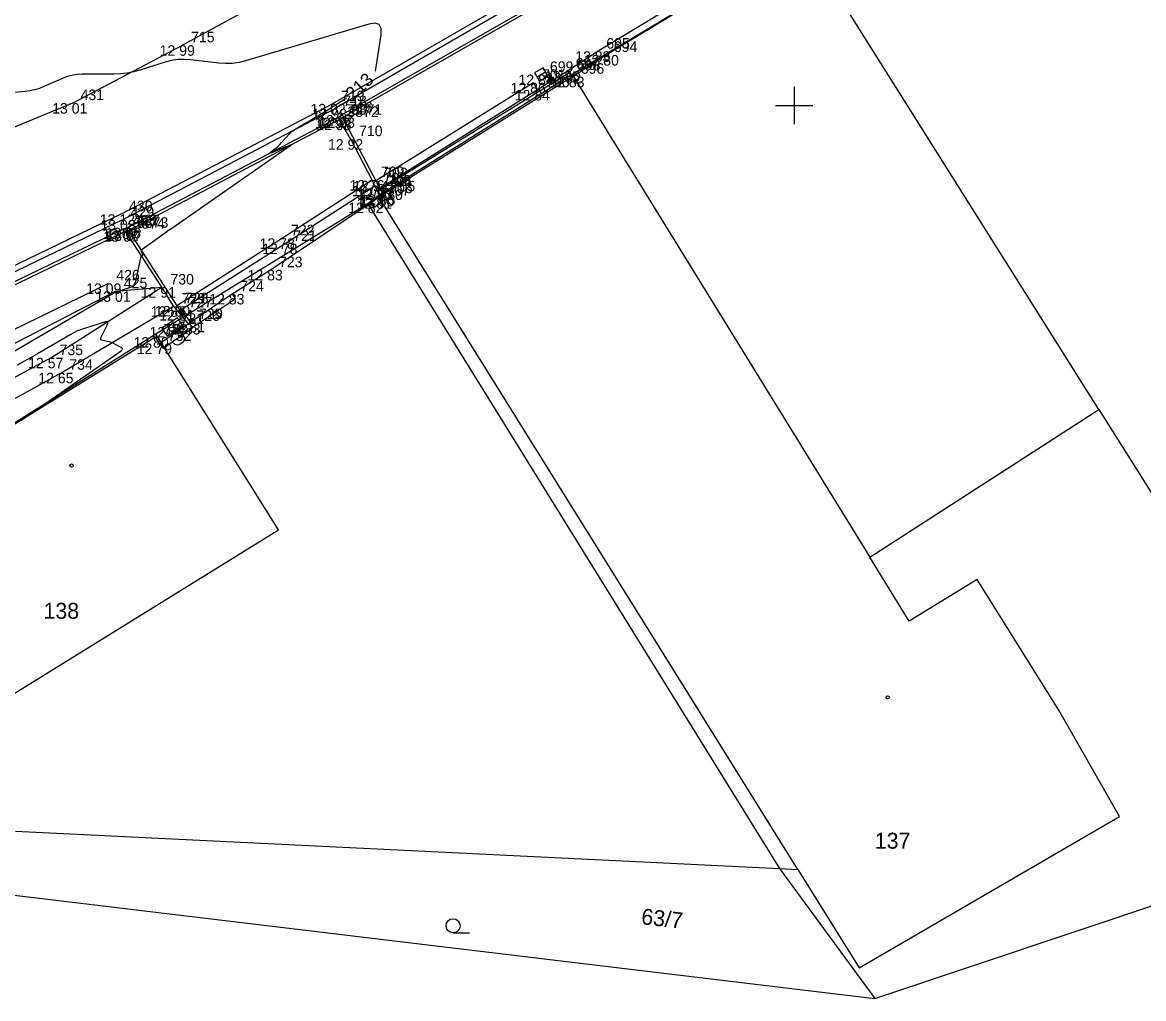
# Model space of a CAD drawing. Extents: x -703403 to -701924, y -1022520 to -1021856.
# Drawn here: x -703295.54 to -703265.7, y -1022198.78 to -1022172.79 of the extents above; entities that cross this region are included whole.
import ezdxf

# ---------------------------------------------------------------- set-up
doc = ezdxf.new("R2010")
doc.units = 0
for name, color, linetype in [('Ex_Contour Labels', 7, 'Continuous'), ('Ex_Major Contours', 7, 'Continuous'), ('Ex_Minor Contours', 7, 'Continuous'), ('Z_body', 7, 'Continuous'), ('Z_body_cisla', 7, 'Continuous'), ('Z_body_vysky_redukovane', 7, 'Continuous'), ('Z_budova', 7, 'Continuous'), ('Z_chodnik', 7, 'Continuous'), ('Z_hektometricka_sit', 7, 'Continuous'), ('Z_hrany_paty', 7, 'Continuous'), ('Z_katastr_cisla_pozemkova', 7, 'Continuous'), ('Z_katastr_cisla_stavebni', 7, 'Continuous'), ('Z_katastr_hranice', 7, 'Continuous'), ('Z_katastr_vnitrni_kresba', 7, 'Continuous'), ('Z_katastr_znacky_budov', 7, 'Continuous'), ('Z_katastr_znacky_kultur', 7, 'Continuous'), ('Z_komunikace', 7, 'Continuous'), ('Z_komunikace_osa', 7, 'Continuous'), ('Z_obruba', 7, 'Continuous'), ('Z_pilire', 7, 'Continuous'), ('Z_ploty', 7, 'Continuous'), ('Z_ploty_znacky', 7, 'Continuous'), ('Z_rozhranni', 7, 'Continuous'), ('Z_site_kanalizace_znaky', 7, 'Continuous'), ('Z_svodidla', 7, 'Continuous'), ('Z_vstupy', 7, 'Continuous'), ('Z_zlabek', 7, 'Continuous')]:
    doc.layers.add(name, color=color, linetype=linetype)

# ---------------------------------------------------------------- blocks, each defined once
blk = doc.blocks.new('POINT_DISPLAY')
blk.add_line((0, 0), (0, 0))
blk = doc.blocks.new('Z666')
for p, q in [((-0.25, 0.13), (-0.25, -0.13)), ((0.25, 0.13), (-0.25, 0.13)), ((0.25, -0.13), (0.25, 0.13)), ((-0.25, -0.13), (0.25, -0.13))]:
    blk.add_line(p, q)
blk = doc.blocks.new('Z46260')
for p, q in [((0.13, 0.13), (-0.13, 0.13)), ((-0.13, 0.13), (-0.13, -0.13)), ((0.13, 0), (-0.13, 0)), ((0.13, -0.13), (0.13, 0.13)), ((-0.13, -0.13), (0.13, -0.13))]:
    blk.add_line(p, q)
blk = doc.blocks.new('Z216')
for p, q in [((-0.17, 0), (-0.15, 0.1)), ((-0.15, 0.1), (-0.1, 0.15)), ((-0.1, 0.15), (-0.03, 0.17)), ((-0.03, 0.17), (0.03, 0.17)), ((0.03, 0.17), (0.1, 0.15)), ((0.1, 0.15), (0.15, 0.1)), ((0.15, 0.1), (0.17, 0))]:
    blk.add_line(p, q)

msp = doc.modelspace()

# ---------------------------------------------------------------- linework, layer by layer
at = {"layer": 'Ex_Major Contours'}
for points in [[(-703286.143, -1022174.09), (-703285.992, -1022173.119), (-703285.989, -1022172.952), (-703286.042, -1022172.849), (-703286.152, -1022172.81), (-703286.317, -1022172.836), (-703289.599, -1022173.815), (-703289.775, -1022173.858), (-703289.953, -1022173.883), (-703290.133, -1022173.889), (-703290.314, -1022173.877), (-703291.058, -1022173.788), (-703291.231, -1022173.776), (-703291.403, -1022173.783), (-703291.573, -1022173.808), (-703291.741, -1022173.852), (-703292.41, -1022174.064), (-703292.579, -1022174.11), (-703292.749, -1022174.144), (-703292.922, -1022174.164), (-703293.096, -1022174.171), (-703293.96, -1022174.173), (-703294.092, -1022174.18), (-703294.222, -1022174.201), (-703294.349, -1022174.235), (-703294.474, -1022174.282), (-703294.965, -1022174.498), (-703295.089, -1022174.547), (-703295.215, -1022174.585), (-703295.345, -1022174.614), (-703295.477, -1022174.631), (-703298.928, -1022174.96)], [(-703296.239, -1022181.823), (-703293.136, -1022180.012), (-703293.117, -1022180.001), (-703293.098, -1022179.992), (-703293.079, -1022179.984), (-703293.059, -1022179.977), (-703292.978, -1022179.952), (-703292.957, -1022179.945), (-703292.937, -1022179.938), (-703292.917, -1022179.931), (-703292.897, -1022179.924), (-703292.643, -1022179.827), (-703292.599, -1022179.805), (-703292.564, -1022179.774), (-703292.539, -1022179.735), (-703292.523, -1022179.687), (-703292.378, -1022179.013), (-703292.376, -1022179.008), (-703292.373, -1022179.004), (-703292.369, -1022179.001), (-703292.364, -1022178.999), (-703292.342, -1022178.993), (-703292.337, -1022178.992), (-703292.334, -1022178.989), (-703292.334, -1022178.985), (-703292.335, -1022178.98), (-703292.372, -1022178.886), (-703292.376, -1022178.869), (-703292.375, -1022178.854), (-703292.368, -1022178.841), (-703292.355, -1022178.829), (-703291.894, -1022178.498), (-703291.812, -1022178.44), (-703291.73, -1022178.381), (-703291.647, -1022178.323), (-703291.565, -1022178.266), (-703288.392, -1022176.06), (-703288.379, -1022176.05), (-703288.376, -1022176.046), (-703288.382, -1022176.046), (-703288.397, -1022176.052), (-703288.477, -1022176.084), (-703288.497, -1022176.092), (-703288.517, -1022176.1), (-703288.537, -1022176.108), (-703288.557, -1022176.117), (-703288.925, -1022176.27), (-703288.959, -1022176.282), (-703288.973, -1022176.283), (-703288.966, -1022176.271), (-703288.938, -1022176.248), (-703288.788, -1022176.131), (-703288.751, -1022176.1), (-703288.716, -1022176.069), (-703288.681, -1022176.036), (-703288.649, -1022176.001), (-703288.422, -1022175.751), (-703288.39, -1022175.718), (-703288.356, -1022175.687), (-703288.319, -1022175.659), (-703288.281, -1022175.634), (-703288.122, -1022175.539), (-703288.082, -1022175.515), (-703288.043, -1022175.492), (-703288.003, -1022175.468), (-703287.963, -1022175.444), (-703287.456, -1022175.142), (-703287.358, -1022175.083), (-703287.261, -1022175.023), (-703287.165, -1022174.963), (-703287.069, -1022174.901), (-703286.915, -1022174.802)]]:
    msp.add_lwpolyline(points, dxfattribs=at)
at = {"layer": 'Ex_Minor Contours'}
msp.add_lwpolyline([(-703295.579, -1022183.387), (-703292.91, -1022181.538), (-703292.883, -1022181.513), (-703292.875, -1022181.489), (-703292.885, -1022181.466), (-703292.915, -1022181.444), (-703293.077, -1022181.356), (-703293.115, -1022181.337), (-703293.153, -1022181.321), (-703293.192, -1022181.308), (-703293.233, -1022181.297), (-703293.397, -1022181.261), (-703293.431, -1022181.249), (-703293.449, -1022181.229), (-703293.453, -1022181.202), (-703293.441, -1022181.168), (-703293.283, -1022180.854), (-703293.264, -1022180.8), (-703293.269, -1022180.768), (-703293.3, -1022180.757), (-703293.357, -1022180.768), (-703293.862, -1022180.928), (-703293.968, -1022180.965), (-703294.071, -1022181.007), (-703294.172, -1022181.055), (-703294.271, -1022181.109), (-703295.142, -1022181.618), (-703295.32, -1022181.72), (-703295.499, -1022181.821), (-703295.679, -1022181.92)], dxfattribs=at)
at = {"layer": 'Z_budova'}
for p, q in [((-703280.91, -1022174.24), (-703285.94, -1022177.37)), ((-703286, -1022177.41), (-703286.08, -1022177.47)), ((-703285.94, -1022177.37), (-703286, -1022177.41)), ((-703286.08, -1022177.47), (-703285.99, -1022177.59)), ((-703292, -1022181.17), (-703300.59, -1022186.49)), ((-703291.89, -1022181.34), (-703292, -1022181.17)), ((-703291.89, -1022181.34), (-703291.8, -1022181.46))]:
    msp.add_line(p, q, dxfattribs=at)
at = {"layer": 'Z_chodnik'}
for p, q in [((-703281.03, -1022174.09), (-703281.83, -1022174.59)), ((-703281.83, -1022174.59), (-703286.03, -1022177.21))]:
    msp.add_line(p, q, dxfattribs=at)
at = {"layer": 'Z_hektometricka_sit'}
for p, q in [((-703275, -1022174.5), (-703275, -1022175.5)), ((-703275.5, -1022175), (-703274.5, -1022175))]:
    msp.add_line(p, q, dxfattribs=at)
at = {"layer": 'Z_hrany_paty'}
for p, q in [((-703297.17, -1022182.07), (-703293.06, -1022179.95)), ((-703293.06, -1022179.95), (-703291.83, -1022179.84))]:
    msp.add_line(p, q, dxfattribs=at)
at = {"layer": 'Z_katastr_hranice'}
for p, q in [((-703274.81, -1022170.51), (-703280.91, -1022174.18)), ((-703266.89, -1022183.1), (-703274.81, -1022170.51)), ((-703280.91, -1022174.18), (-703286.07, -1022177.41)), ((-703286.07, -1022177.41), (-703286.35, -1022177.62)), ((-703286.35, -1022177.62), (-703291.99, -1022181.09)), ((-703286.35, -1022177.62), (-703275.39, -1022195.32)), ((-703291.99, -1022181.09), (-703300.54, -1022186.47)), ((-703272.99, -1022187.03), (-703266.89, -1022183.1)), ((-703266.89, -1022183.1), (-703259.79, -1022194.4)), ((-703271.94, -1022188.73), (-703272.99, -1022187.03)), ((-703270.13, -1022187.62), (-703271.94, -1022188.73)), ((-703267.96, -1022191.1), (-703270.13, -1022187.62)), ((-703266.34, -1022193.93), (-703267.96, -1022191.1)), ((-703319.68, -1022193.15), (-703272.85, -1022198.78)), ((-703273.27, -1022197.96), (-703266.34, -1022193.93)), ((-703295.72, -1022194.32), (-703275.39, -1022195.32)), ((-703272.85, -1022198.78), (-703259.79, -1022194.4)), ((-703275.39, -1022195.32), (-703272.85, -1022198.78)), ((-703275.39, -1022195.32), (-703274.9, -1022195.34)), ((-703274.9, -1022195.34), (-703273.27, -1022197.96))]:
    msp.add_line(p, q, dxfattribs=at)
at = {"layer": 'Z_katastr_vnitrni_kresba'}
for p, q in [((-703280.91, -1022174.18), (-703272.99, -1022187.03)), ((-703278.08, -1022190.24), (-703286.07, -1022177.41)), ((-703288.72, -1022186.3), (-703291.99, -1022181.09)), ((-703297.36, -1022191.65), (-703288.72, -1022186.3)), ((-703274.9, -1022195.34), (-703278.08, -1022190.24))]:
    msp.add_line(p, q, dxfattribs=at)
at = {"layer": 'Z_katastr_znacky_budov'}
for centre in [(-703294.232, -1022184.59), (-703272.512, -1022190.76)]:
    msp.add_circle(centre, 0.0437, dxfattribs=at)
at = {"layer": 'Z_katastr_znacky_kultur'}
msp.add_line((-703284.078, -1022197.03), (-703283.641, -1022197.03), dxfattribs=at)
msp.add_circle((-703284.078, -1022196.842), 0.187, dxfattribs=at)
at = {"layer": 'Z_komunikace'}
for p, q in [((-703282.29, -1022172.07), (-703287.29, -1022174.96)), ((-703292.92, -1022177.9), (-703287.29, -1022174.96)), ((-703292.92, -1022177.9), (-703298.28, -1022180.49))]:
    msp.add_line(p, q, dxfattribs=at)
at = {"layer": 'Z_komunikace_osa'}
for p, q in [((-703283.89, -1022169.36), (-703291.28, -1022173.4)), ((-703294.21, -1022174.94), (-703291.28, -1022173.4)), ((-703294.21, -1022174.94), (-703299.59, -1022177.17))]:
    msp.add_line(p, q, dxfattribs=at)
at = {"layer": 'Z_obruba'}
for p, q in [((-703282.25, -1022172.21), (-703287.23, -1022175.09)), ((-703287.02, -1022175.32), (-703282.07, -1022172.49)), ((-703281, -1022174.14), (-703286.01, -1022177.24)), ((-703292.88, -1022178.05), (-703287.23, -1022175.09)), ((-703287.11, -1022175.38), (-703287.02, -1022175.32)), ((-703287.02, -1022175.32), (-703286.13, -1022177.01)), ((-703292.72, -1022178.33), (-703287.11, -1022175.38)), ((-703286.13, -1022177.01), (-703286.03, -1022177.21)), ((-703286.03, -1022177.21), (-703286.01, -1022177.24)), ((-703286.01, -1022177.24), (-703285.94, -1022177.37)), ((-703292.88, -1022178.05), (-703298.2, -1022180.61)), ((-703298.01, -1022180.87), (-703292.8, -1022178.35)), ((-703292.8, -1022178.35), (-703292.72, -1022178.33)), ((-703291.83, -1022179.84), (-703292.8, -1022178.35)), ((-703291.52, -1022180.35), (-703291.83, -1022179.84)), ((-703291.52, -1022180.35), (-703291.13, -1022180.82))]:
    msp.add_line(p, q, dxfattribs=at)
at = {"layer": 'Z_ploty'}
for p, q in [((-703286.08, -1022177.47), (-703286.26, -1022177.59)), ((-703286.17, -1022177.72), (-703286.26, -1022177.59)), ((-703285.99, -1022177.59), (-703286.17, -1022177.72)), ((-703291.06, -1022180.76), (-703289.96, -1022180.02)), ((-703289.96, -1022180.02), (-703289.88, -1022180.15)), ((-703290.97, -1022180.88), (-703289.88, -1022180.15)), ((-703291.89, -1022181.34), (-703291.13, -1022180.82)), ((-703291.8, -1022181.46), (-703291.03, -1022180.94)), ((-703291.13, -1022180.82), (-703291.06, -1022180.76)), ((-703291.03, -1022180.94), (-703290.97, -1022180.88))]:
    msp.add_line(p, q, dxfattribs=at)
at = {"layer": 'Z_rozhranni'}
for p, q in [((-703286.8, -1022175.9), (-703287.11, -1022175.38)), ((-703286.23, -1022176.99), (-703286.8, -1022175.9)), ((-703286.16, -1022177.14), (-703286.23, -1022176.99)), ((-703286, -1022177.41), (-703286.16, -1022177.14)), ((-703292.72, -1022178.33), (-703291.43, -1022180.34)), ((-703291.34, -1022180.45), (-703291.43, -1022180.34)), ((-703291.34, -1022180.45), (-703291.06, -1022180.76))]:
    msp.add_line(p, q, dxfattribs=at)
at = {"layer": 'Z_svodidla'}
msp.add_line((-703297.52, -1022181.82), (-703293.26, -1022179.74), dxfattribs=at)
at = {"layer": 'Z_vstupy'}
for p, q in [((-703280.02, -1022173.66), (-703276.98, -1022171.82)), ((-703280.91, -1022174.24), (-703280.02, -1022173.66)), ((-703288.94, -1022179.38), (-703286.26, -1022177.59)), ((-703289.96, -1022180.02), (-703288.94, -1022179.38))]:
    msp.add_line(p, q, dxfattribs=at)
at = {"layer": 'Z_zlabek'}
for p, q in [((-703276.14, -1022171.09), (-703280.22, -1022173.56)), ((-703287.06, -1022175.26), (-703282.11, -1022172.43)), ((-703280.22, -1022173.56), (-703281.03, -1022174.09)), ((-703281.03, -1022174.09), (-703281, -1022174.14)), ((-703281.94, -1022174.4), (-703286.13, -1022177.01)), ((-703281.94, -1022174.4), (-703281.83, -1022174.59)), ((-703281, -1022174.14), (-703280.91, -1022174.24)), ((-703287.15, -1022175.33), (-703292.74, -1022178.26)), ((-703287.15, -1022175.33), (-703287.06, -1022175.26)), ((-703286.23, -1022176.99), (-703288.62, -1022178.54)), ((-703288.55, -1022178.68), (-703286.16, -1022177.14)), ((-703298.04, -1022180.8), (-703292.83, -1022178.28)), ((-703292.83, -1022178.28), (-703292.74, -1022178.26)), ((-703288.62, -1022178.54), (-703291.43, -1022180.34)), ((-703291.34, -1022180.45), (-703288.55, -1022178.68)), ((-703294.78, -1022181.72), (-703291.83, -1022179.84)), ((-703294.51, -1022182.12), (-703291.52, -1022180.35)), ((-703294.78, -1022181.72), (-703298.53, -1022183.76)), ((-703298.36, -1022184.25), (-703294.51, -1022182.12))]:
    msp.add_line(p, q, dxfattribs=at)

# ---------------------------------------------------------------- block references
at = {"layer": 'Z_body'}
for p in [(-703291.28, -1022173.4), (-703280.22, -1022173.56), (-703280.02, -1022173.66), (-703281.03, -1022174.09), (-703281.94, -1022174.4), (-703281.73, -1022174.18), (-703281, -1022174.14), (-703280.91, -1022174.24), (-703281.83, -1022174.59), (-703294.21, -1022174.94), (-703287.29, -1022174.96), (-703287.23, -1022175.09), (-703287.15, -1022175.33), (-703287.06, -1022175.26), (-703287.02, -1022175.32), (-703287.11, -1022175.38), (-703286.8, -1022175.9), (-703286.23, -1022176.99), (-703286.13, -1022177.01), (-703286.16, -1022177.14), (-703286.03, -1022177.21), (-703286.01, -1022177.24), (-703286, -1022177.41), (-703285.94, -1022177.37), (-703286.26, -1022177.59), (-703286.08, -1022177.47), (-703292.92, -1022177.9), (-703292.88, -1022178.05), (-703292.83, -1022178.28), (-703292.74, -1022178.26), (-703292.8, -1022178.35), (-703292.72, -1022178.33), (-703288.62, -1022178.54), (-703288.55, -1022178.68), (-703288.94, -1022179.38), (-703293.26, -1022179.74), (-703293.06, -1022179.95), (-703291.83, -1022179.84), (-703289.96, -1022180.02), (-703291.52, -1022180.35), (-703291.43, -1022180.34), (-703291.34, -1022180.45), (-703291.55, -1022180.9), (-703291.13, -1022180.82), (-703291.06, -1022180.76), (-703292, -1022181.17), (-703291.89, -1022181.34), (-703294.78, -1022181.72), (-703294.51, -1022182.12)]:
    msp.add_blockref('POINT_DISPLAY', p, dxfattribs=at)
at = {"layer": 'Z_pilire', "rotation": 33.3}
msp.add_blockref('Z666', (-703291.55, -1022180.9), dxfattribs=at)
at = {"layer": 'Z_ploty_znacky'}
for p, rotation in [((-703290.42, -1022180.51), -146.30000000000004), ((-703291.41, -1022181.2), -145.5)]:
    msp.add_blockref('Z216', p, dxfattribs=dict(at, rotation=rotation))
at = {"layer": 'Z_site_kanalizace_znaky', "rotation": 30.599999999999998}
msp.add_blockref('Z46260', (-703281.73, -1022174.18), dxfattribs=at)

# ---------------------------------------------------------------- texts
at = {"layer": 'Ex_Contour Labels'}
msp.add_text('213', height=0.35, rotation=42.197, dxfattribs=at).set_placement((-703286.742, -1022174.885))
at = {"layer": 'Z_body_cisla'}
for s, p in [('715', (-703291.05, -1022173.32)), ('695', (-703280, -1022173.49)), ('694', (-703279.8, -1022173.58)), ('699', (-703281.5, -1022174.11)), ('697', (-703280.81, -1022174.02)), ('698', (-703280.78, -1022174.07)), ('701', (-703281.71, -1022174.32)), ('696', (-703280.68, -1022174.16)), ('700', (-703281.6, -1022174.52)), ('431', (-703293.99, -1022174.86)), ('719', (-703287.06, -1022174.89)), ('718', (-703287, -1022175.02)), ('717', (-703286.92, -1022175.25)), ('3872', (-703286.89, -1022175.31)), ('716', (-703286.84, -1022175.19)), ('3871', (-703286.8, -1022175.25)), ('710', (-703286.58, -1022175.82)), ('709', (-703286, -1022176.91)), ('708', (-703285.93, -1022177.07)), ('702', (-703285.91, -1022176.94)), ('707', (-703285.85, -1022177.4)), ('703', (-703285.81, -1022177.14)), ('704', (-703285.79, -1022177.17)), ('706', (-703285.78, -1022177.34)), ('705', (-703285.71, -1022177.29)), ('720', (-703286.04, -1022177.52)), ('430', (-703292.7, -1022177.82)), ('429', (-703292.66, -1022177.98)), ('428', (-703292.6, -1022178.2)), ('3874', (-703292.58, -1022178.28)), ('427', (-703292.51, -1022178.19)), ('3873', (-703292.49, -1022178.26)), ('722', (-703288.39, -1022178.46)), ('721', (-703288.33, -1022178.61)), ('723', (-703288.71, -1022179.31)), ('426', (-703293.04, -1022179.66)), ('730', (-703291.6, -1022179.77)), ('425', (-703292.84, -1022179.87)), ('724', (-703289.74, -1022179.95)), ('729', (-703291.3, -1022180.28)), ('728', (-703291.21, -1022180.27)), ('727', (-703291.11, -1022180.38)), ('731', (-703291.33, -1022180.82)), ('726', (-703290.91, -1022180.74)), ('725', (-703290.84, -1022180.69)), ('733', (-703291.78, -1022181.1)), ('732', (-703291.67, -1022181.27)), ('735', (-703294.55, -1022181.65)), ('734', (-703294.29, -1022182.04))]:
    msp.add_text(s, height=0.28, dxfattribs=at).set_placement(p)
at = {"layer": 'Z_body_vysky_redukovane'}
for s, p in [('12 99', (-703291.887, -1022173.68)), ('12 83', (-703280.827, -1022173.84)), ('12 80', (-703280.603, -1022173.94)), ('12 85', (-703281.637, -1022174.37)), ('12 92', (-703281.607, -1022174.42)), ('12 86', (-703282.547, -1022174.68)), ('12 84', (-703282.337, -1022174.46)), ('12 83', (-703281.517, -1022174.52)), ('12 84', (-703282.437, -1022174.87)), ('13 01', (-703294.747, -1022175.22)), ('13 02', (-703287.873, -1022175.24)), ('12 98', (-703287.837, -1022175.37)), ('12 97', (-703287.757, -1022175.61)), ('12 97', (-703287.667, -1022175.54)), ('12 98', (-703287.627, -1022175.6)), ('12 98', (-703287.717, -1022175.66)), ('12 92', (-703287.407, -1022176.18)), ('12 76', (-703286.837, -1022177.27)), ('12 94', (-703286.737, -1022177.29)), ('12 75', (-703286.767, -1022177.42)), ('12 93', (-703286.637, -1022177.49)), ('12 93', (-703286.617, -1022177.52)), ('12 80', (-703286.583, -1022177.69)), ('12 93', (-703286.547, -1022177.65)), ('12 82', (-703286.867, -1022177.87)), ('12 81', (-703286.64, -1022177.75)), ('13 12', (-703293.48, -1022178.18)), ('13 08', (-703293.463, -1022178.33)), ('13 07', (-703293.413, -1022178.56)), ('13 06', (-703293.323, -1022178.54)), ('13 07', (-703293.383, -1022178.63)), ('13 07', (-703293.303, -1022178.61)), ('12 78', (-703289.227, -1022178.82)), ('12 78', (-703289.157, -1022178.96)), ('12 83', (-703289.547, -1022179.66)), ('13 09', (-703293.843, -1022180.02)), ('13 01', (-703293.597, -1022180.23)), ('12 91', (-703292.39, -1022180.12)), ('12 83', (-703290.567, -1022180.3)), ('12 87', (-703292.127, -1022180.63)), ('12 80', (-703292.013, -1022180.62)), ('12 81', (-703291.9, -1022180.73)), ('12 78', (-703292.157, -1022181.18)), ('12 83', (-703291.737, -1022181.1)), ('12 81', (-703291.62, -1022181.04)), ('12 80', (-703292.583, -1022181.45)), ('12 79', (-703292.497, -1022181.62)), ('12 57', (-703295.387, -1022182)), ('12 65', (-703295.117, -1022182.4))]:
    msp.add_text(s, height=0.28, dxfattribs=at).set_placement(p)
at = {"layer": 'Z_katastr_cisla_pozemkova'}
msp.add_text('63/7', height=0.425, rotation=354, dxfattribs=at).set_placement((-703279.084, -1022196.801))
at = {"layer": 'Z_katastr_cisla_stavebni'}
for s, p in [('138', (-703294.979, -1022188.669)), ('137', (-703272.854, -1022194.789))]:
    msp.add_text(s, height=0.425, dxfattribs=at).set_placement(p)

doc.saveas('drawing.dxf')
